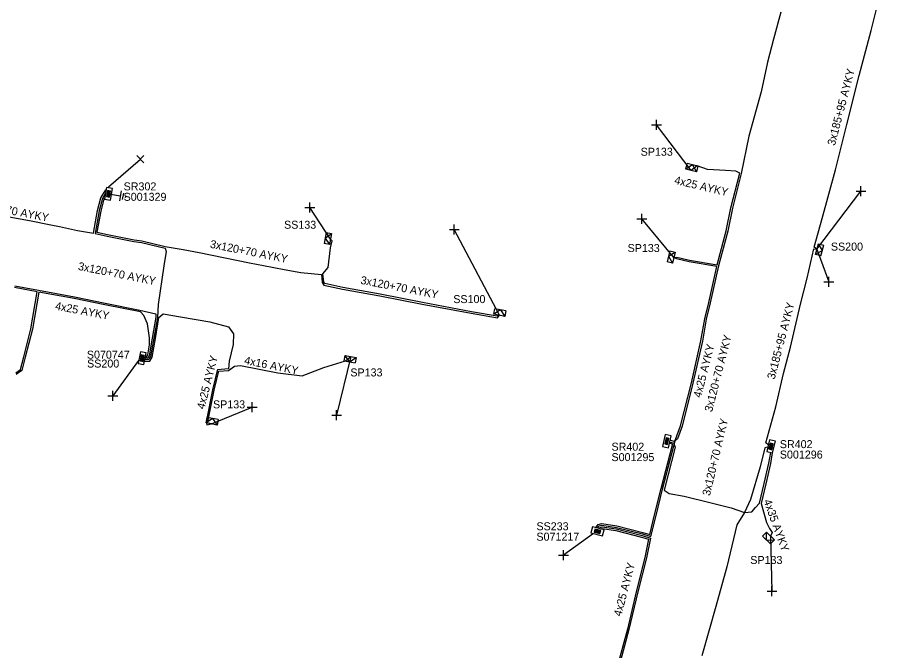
# Model space of a CAD drawing. Extents: x -763093 to -760976, y -1155572 to -1152009.
# Drawn here: x -762038.3 to -761930.3, y -1154750.4 to -1154671.3 of the extents above; entities that cross this region are included whole.
import ezdxf

# ---------------------------------------------------------------- set-up
doc = ezdxf.new("R2010")
doc.units = 0
for name, color, linetype in [('Vrstva 1', 7, 'Continuous'), ('Vrstva 14', 7, 'Continuous'), ('Vrstva 15', 7, 'Continuous'), ('Vrstva 28', 7, 'Continuous'), ('Vrstva 29', 7, 'Continuous'), ('Vrstva 30', 7, 'Continuous'), ('Vrstva 31', 7, 'Continuous'), ('Vrstva 33', 7, 'Continuous'), ('Vrstva 34', 7, 'Continuous'), ('Vrstva 5', 7, 'Continuous'), ('Vrstva 59', 7, 'Continuous'), ('Vrstva 6', 7, 'Continuous'), ('Vrstva 8', 7, 'Continuous'), ('Vrstva 9', 7, 'Continuous')]:
    doc.layers.add(name, color=color, linetype=linetype)

# ---------------------------------------------------------------- blocks, each defined once
blk = doc.blocks.new('NN800')
at = {"layer": 'Vrstva 1'}
for points in [[(-0.44, 0.44), (0.44, -0.44)], [(-0.44, -0.44), (0.44, 0.44)]]:
    blk.add_lwpolyline(points, dxfattribs=at)
blk = doc.blocks.new('NN620')
at = {"layer": 'Vrstva 8'}
for points in [[(0.75, 0), (-0.75, 0)], [(-0.75, 0), (-0.75, -0.75)], [(0.75, -0.75), (0.75, 0)], [(-0.75, -0.75), (0.75, -0.75)], [(0.37, -0.18), (-0.38, -0.18)], [(-0.38, -0.18), (-0.38, -0.56)], [(-0.38, -0.56), (0.37, -0.56)], [(0.32, -0.23), (-0.33, -0.23)], [(-0.33, -0.23), (-0.33, -0.51)], [(-0.33, -0.51), (0.32, -0.51)], [(0.27, -0.27), (-0.28, -0.27)], [(-0.28, -0.27), (-0.28, -0.46)], [(-0.28, -0.46), (0.27, -0.46)], [(0.23, -0.32), (-0.23, -0.32)], [(-0.23, -0.32), (-0.23, -0.42)], [(-0.23, -0.42), (0.23, -0.42)], [(-0.19, -0.37), (0.19, -0.37)], [(0.23, -0.42), (0.23, -0.32)], [(0.27, -0.46), (0.27, -0.27)], [(0.32, -0.51), (0.32, -0.23)], [(0.37, -0.56), (0.37, -0.18)]]:
    blk.add_lwpolyline(points, dxfattribs=at)
blk = doc.blocks.new('NN630')
at = {"layer": 'Vrstva 9'}
for points in [[(0, -0.7), (-0.7, 0)], [(-0.7, -0.7), (-0.7, 0), (0.7, 0), (0.7, -0.7)], [(-0.7, -0.7), (0.7, -0.7)], [(0, -0.7), (0.7, 0)]]:
    blk.add_lwpolyline(points, dxfattribs=at)
blk = doc.blocks.new('NN810')
at = {"layer": 'Vrstva 14'}
for points in [[(0, -0.64), (0, -1.89)], [(0.63, -1.89), (-0.62, -1.89)], [(0.39, -2.2), (-0.4, -2.2)], [(0, -2.52), (-0.12, -2.52)], [(0.14, -2.52), (0, -2.52)]]:
    blk.add_lwpolyline(points, dxfattribs=at)

msp = doc.modelspace()

# ---------------------------------------------------------------- linework, layer by layer
at = {"layer": 'Vrstva 5'}
for points in [[(-761944.48, -1154724.71), (-761944.78, -1154724.46), (-761943.53, -1154719.99), (-761942.54, -1154715.82), (-761941.67, -1154712.51), (-761940.43, -1154707.17), (-761939.62, -1154703.9), (-761938.78, -1154700.25), (-761938.38, -1154700.28), (-761938.73, -1154700.05), (-761937.72, -1154696.43), (-761936.08, -1154690.36), (-761934.63, -1154684.7), (-761933.1, -1154678.6), (-761931.62, -1154672.98), (-761930.29, -1154667.61)], [(-761942.9, -1154670.66), (-761943.82, -1154674.06), (-761944.56, -1154676.94), (-761945.35, -1154680.61), (-761946.88, -1154686.16), (-761947.83, -1154690.83), (-761948.93, -1154695.15), (-761949.53, -1154698.05), (-761950.69, -1154702.38), (-761951.71, -1154706.98), (-761952.21, -1154709.04), (-761952.69, -1154711.78), (-761953.87, -1154717.04), (-761955.24, -1154722.4), (-761955.81, -1154723.98), (-761956.23, -1154724.3), (-761956.65, -1154724.18)], [(-762054.81, -1154687.88), (-762054.62, -1154688.41), (-762055.22, -1154691.2), (-762055.63, -1154693.29), (-762052.3, -1154693.64), (-762048.76, -1154694.41), (-762046.1, -1154694.95), (-762043.74, -1154695.37), (-762040.22, -1154696.08), (-762036.78, -1154696.7), (-762034.12, -1154697.24), (-762033, -1154697.43), (-762030.78, -1154697.94), (-762028.78, -1154698.28), (-762028.27, -1154695.46), (-762027.85, -1154693.88), (-762027.24, -1154692.86)], [(-761965.75, -1154735.06), (-761965.59, -1154734.86), (-761965.24, -1154734.75), (-761963.43, -1154735.04), (-761960.18, -1154735.86), (-761959.13, -1154736.18), (-761958.46, -1154733.55), (-761957.67, -1154730.25), (-761956.25, -1154724.86), (-761956.04, -1154724.06), (-761955.44, -1154722.34), (-761954.07, -1154717), (-761952.89, -1154711.74), (-761952.41, -1154709), (-761951.91, -1154706.94), (-761950.91, -1154702.43), (-761954.34, -1154701.86), (-761955.94, -1154701.5), (-761956.25, -1154701.33), (-761955.9, -1154701.3), (-761954.3, -1154701.66), (-761950.86, -1154702.24), (-761949.73, -1154698.01), (-761949.13, -1154695.11), (-761948.02, -1154690.77), (-761948.52, -1154690.54), (-761949.8, -1154690.47), (-761952.07, -1154690.34), (-761953.35, -1154689.87), (-761954.1, -1154690.44)], [(-762027.27, -1154693.3), (-762027.66, -1154693.96), (-762028.07, -1154695.5), (-762028.58, -1154698.31), (-762027.07, -1154698.65), (-762023.73, -1154699.31), (-762022.77, -1154699.46), (-762019.82, -1154700.17), (-762019.71, -1154700.58), (-762019.99, -1154702.37), (-762020.7, -1154707.19), (-762020.79, -1154708.8), (-762021.24, -1154711.42), (-762021.64, -1154713.69), (-762021.85, -1154714.08), (-762022.32, -1154714.06)], [(-762027.41, -1154693.93), (-762027.47, -1154694.04), (-762027.87, -1154695.54), (-762028.35, -1154698.16), (-762027.03, -1154698.45), (-762023.69, -1154699.11), (-762022.73, -1154699.26), (-762019.83, -1154699.96), (-762017.57, -1154700.34), (-762015.55, -1154700.7), (-762009.27, -1154701.98), (-762007.55, -1154702.32), (-762004.95, -1154702.83), (-762002.88, -1154703.19), (-762000.3, -1154703.46), (-762000.2, -1154704.45), (-762000, -1154704.77), (-761997.67, -1154705.28), (-761992.98, -1154706.1), (-761987.69, -1154707.15), (-761981.58, -1154708.29), (-761978.29, -1154708.86), (-761978.06, -1154708.54), (-761978.35, -1154708.64), (-761981.54, -1154708.09), (-761987.65, -1154706.95), (-761992.94, -1154705.9), (-761997.63, -1154705.08), (-761999.88, -1154704.59), (-762000, -1154704.39), (-762000.11, -1154703.36), (-761999.45, -1154702.59), (-761999.15, -1154700.13), (-761998.97, -1154699.22), (-761999.15, -1154699.03)], [(-762038.49, -1154715.73), (-762037.89, -1154715.31), (-762037.49, -1154713.74), (-762036.61, -1154710.22), (-762035.8, -1154705.6), (-762038.63, -1154705.06)], [(-762038.59, -1154704.86), (-762035.66, -1154705.42), (-762031.16, -1154706.24), (-762027.33, -1154707.02), (-762022.99, -1154707.89), (-762020.97, -1154708.35), (-762020.99, -1154708.77), (-762021.44, -1154711.38), (-762021.82, -1154713.59), (-762021.97, -1154713.88), (-762022.22, -1154713.87)], [(-762022.2, -1154713.67), (-762022.09, -1154713.68), (-762022, -1154713.5), (-762021.77, -1154712.25), (-762021.79, -1154711.34), (-762022.04, -1154709.59), (-762022.48, -1154708.58), (-762022.9, -1154708.11), (-762027.37, -1154707.22), (-762031.2, -1154706.44), (-762035.6, -1154705.64), (-762036.41, -1154710.26), (-762037.29, -1154713.78), (-762037.71, -1154715.43), (-762038.43, -1154715.93)], [(-762022.36, -1154714.28), (-762021.73, -1154714.28), (-762021.46, -1154713.78), (-762021.04, -1154711.46), (-762020.59, -1154708.83), (-762020.06, -1154708.35), (-762017.9, -1154708.73), (-762014.22, -1154709.38), (-762011.89, -1154709.98), (-762011.3, -1154710.84), (-762011.31, -1154712.21), (-762011.84, -1154714.27), (-762011.92, -1154715.22), (-762013.26, -1154715.35), (-762013.55, -1154716.49), (-762013.89, -1154717.86), (-762014.69, -1154721.85), (-762014.6, -1154722.21), (-762014.02, -1154722.12)], [(-762014.02, -1154722.12), (-762014.44, -1154722.01), (-762014.49, -1154721.85), (-762013.69, -1154717.9), (-762013.35, -1154716.53), (-762013.1, -1154715.53), (-762011.92, -1154715.42), (-762011.16, -1154714.91), (-762010.42, -1154714.8), (-762005.72, -1154715.74), (-762002.68, -1154716.11), (-762000, -1154715.06), (-761997.28, -1154714.23), (-761996.64, -1154713.68)], [(-761956.71, -1154724.38), (-761956.31, -1154724.49), (-761956.08, -1154725), (-761957.49, -1154730.37), (-761956.84, -1154730.82), (-761954.98, -1154731.12), (-761951.77, -1154731.95), (-761949.1, -1154732.61), (-761947.44, -1154733.18), (-761946.5, -1154733.1), (-761946.04, -1154732.55), (-761945.54, -1154732), (-761944.96, -1154729.54), (-761944.38, -1154727), (-761944.16, -1154725.7)], [(-761965.98, -1154735.02), (-761965.71, -1154734.69), (-761965.25, -1154734.54), (-761963.39, -1154734.85), (-761960.13, -1154735.67), (-761959.27, -1154735.93), (-761958.66, -1154733.49), (-761957.86, -1154730.2), (-761956.42, -1154724.72), (-761956.45, -1154724.65), (-761956.75, -1154724.57)], [(-761944.55, -1154725), (-761944.89, -1154725.09), (-761945.46, -1154727.48), (-761946.67, -1154731.56), (-761947.44, -1154733.18), (-761948.41, -1154734.73), (-761949.64, -1154739.95), (-761951, -1154744.92), (-761952.76, -1154751.08)], [(-761943.96, -1154725.73), (-761944.18, -1154727.04), (-761944.76, -1154729.58), (-761945.35, -1154732.05), (-761944.7, -1154734.43), (-761944.31, -1154735.16), (-761943.99, -1154735.66), (-761944.19, -1154736.12)], [(-761965.55, -1154735.13), (-761965.47, -1154735.04), (-761965.22, -1154734.95), (-761963.47, -1154735.24), (-761960.24, -1154736.06), (-761959.17, -1154736.38), (-761959.68, -1154738.85), (-761960.76, -1154743.11), (-761961.87, -1154747.79), (-761963.14, -1154752.5)], [(-761965.33, -1154735.2), (-761965.21, -1154735.16), (-761963.51, -1154735.43), (-761960.29, -1154736.25), (-761959.41, -1154736.52), (-761959.88, -1154738.81), (-761960.96, -1154743.07), (-761962.07, -1154747.75), (-761963.34, -1154752.44)]]:
    msp.add_lwpolyline(points, dxfattribs=at)
at = {"layer": 'Vrstva 59'}
for points in [[(-761954.1, -1154690.44), (-761958.44, -1154684.75)], [(-762026.88, -1154692.48), (-762022.92, -1154689.04)], [(-761938.38, -1154700.28), (-761932.88, -1154693.04)], [(-761999.15, -1154699.03), (-762001.75, -1154695.06)], [(-761956.25, -1154701.33), (-761960.25, -1154696.5)], [(-761978.06, -1154708.54), (-761983.69, -1154697.83)], [(-761938.38, -1154700.28), (-761936.89, -1154704.36)], [(-761996.64, -1154713.68), (-761998.39, -1154721.03)], [(-762023.13, -1154714.2), (-762026.36, -1154718.62)], [(-762014.02, -1154722.12), (-762008.96, -1154720.01)], [(-761966.31, -1154735.8), (-761970.06, -1154738.5)], [(-761944.19, -1154736.12), (-761944, -1154743)]]:
    msp.add_lwpolyline(points, dxfattribs=at)

# ---------------------------------------------------------------- block references
at = {"layer": 'Vrstva 15', "rotation": 79.91701654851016}
msp.add_blockref('NN810', (-762027.27, -1154693.3), dxfattribs=at)
at = {"layer": 'Vrstva 28'}
for p, rotation in [((-762027.27, -1154693.3), 79.91701650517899), ((-762022.32, -1154713.97), -100.96140275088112), ((-761956.78, -1154724.35), -102.84066531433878), ((-761944.48, -1154724.83), 76.00825841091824), ((-761965.71, -1154735.17), -14.524949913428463)]:
    msp.add_blockref('NN620', p, dxfattribs=dict(at, rotation=rotation))
at = {"layer": 'Vrstva 31'}
for p, rotation in [((-761954.1, -1154690.44), 166.37300556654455), ((-761999.15, -1154699.03), -100.8403055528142), ((-761938.38, -1154700.28), 75.56855830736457), ((-761956.25, -1154701.33), -103.6269944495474), ((-761978.06, -1154708.54), 169.01844158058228), ((-761996.64, -1154713.68), -10.75667779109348), ((-762014.02, -1154722.12), 169.27598606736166), ((-761944.19, -1154736.12), -44.67185012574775)]:
    msp.add_blockref('NN630', p, dxfattribs=dict(at, rotation=rotation))
at = {"layer": 'Vrstva 34'}
for p, rotation in [((-761958.44, -1154684.75), 44.99999995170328), ((-761932.88, -1154693.04), 45), ((-762001.75, -1154695.06), 45), ((-761960.25, -1154696.5), 45), ((-761983.69, -1154697.83), 45), ((-761936.89, -1154704.36), 45), ((-762026.36, -1154718.62), 45), ((-762008.96, -1154720.01), 45), ((-761998.39, -1154721.03), 45), ((-761970.06, -1154738.5), 45), ((-761944, -1154743), 45)]:
    msp.add_blockref('NN800', p, dxfattribs=dict(at, rotation=rotation))
msp.add_blockref('NN800', (-762022.92, -1154689.04), dxfattribs=at)

# ---------------------------------------------------------------- texts
at = {"layer": 'Vrstva 29'}
for s, p in [('S001329', (-762025.01, -1154694.24)), ('S070747', (-762029.6, -1154713.96)), ('S001296', (-761943.02, -1154726.44)), ('S001295', (-761964.05, -1154726.76)), ('S071217', (-761973.43, -1154736.7))]:
    msp.add_text(s, height=1, dxfattribs=at).set_placement(p)
at = {"layer": 'Vrstva 30'}
for s, p in [('SR302', (-762025.01, -1154692.94)), ('SS200', (-762029.57, -1154715.07)), ('SR402', (-761964.05, -1154725.46)), ('SR402', (-761943.02, -1154725.14)), ('SS233', (-761973.43, -1154735.4))]:
    msp.add_text(s, height=1, dxfattribs=at).set_placement(p)
at = {"layer": 'Vrstva 33'}
for s, p in [('SP133', (-761960.41, -1154688.61)), ('SS133', (-762004.96, -1154697.73)), ('SP133', (-761962.04, -1154700.64)), ('SS200', (-761936.64, -1154700.46)), ('SS100', (-761983.82, -1154707.02)), ('SP133', (-761996.68, -1154716.18)), ('SP133', (-762013.84, -1154720.17)), ('SP133', (-761946.71, -1154739.61))]:
    msp.add_text(s, height=1, dxfattribs=at).set_placement(p)
at = {"layer": 'Vrstva 6'}
for s, rotation, p in [('3x185+95 AYKY', 75.362, (-761936.14, -1154687.41)), ('4x25 AYKY', 346.661, (-761956.26, -1154692.1)), ('3x120+70 AYKY', 349.144, (-762044.14, -1154694.99)), ('3x120+70 AYKY', 348.797, (-762014.27, -1154700.09)), ('3x120+70 AYKY', 348.753, (-762030.76, -1154702.86)), ('3x120+70 AYKY', 349.018, (-761995.47, -1154704.6)), ('4x25 AYKY', 349.177, (-762033.62, -1154707.82)), ('3x185+95 AYKY', 75.401, (-761943.67, -1154716.61)), ('3x120+70 AYKY', 75.614, (-761951.49, -1154720.68)), ('4x25 AYKY', 75.619, (-761952.88, -1154718.91)), ('4x25 AYKY', 75.668, (-762014.92, -1154720.35)), ('4x16 AYKY', 348.703, (-762009.99, -1154714.62)), ('3x120+70 AYKY', 76.596, (-761951.76, -1154731.16)), ('4x35 AYKY', 289.849, (-761945.07, -1154731.73)), ('4x25 AYKY', 75.264, (-761962.84, -1154746.22))]:
    msp.add_text(s, height=1, rotation=rotation, dxfattribs=at).set_placement(p)

doc.saveas('drawing.dxf')
